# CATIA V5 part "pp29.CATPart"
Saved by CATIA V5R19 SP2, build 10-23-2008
Part number: pp29
Bounding box of the stored display mesh (mm): x -15 to -10, y -102.25 to 75.093, z -52.25 to 37.742
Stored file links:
  C:\Users\Welcome\Documents\thinkm2\pp29.CATPart
  C:\Users\Welcome\Documents\thinkm2\Brasmeca.CATProduct
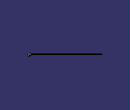
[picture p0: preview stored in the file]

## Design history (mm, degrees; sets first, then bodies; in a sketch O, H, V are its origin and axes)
AxisSystem1: origin (0, 0, 0), X (1, 0, 0), Y (0, 1, 0), Z (0, 0, 1)
Set1
  Plane1: linked copy from another document
  Line1: linked copy from another document
  Plane2: linked copy from another document
Body1 (main body)
  Sketch1 on Plane1, origin (-15, 0, 0), H (0, 1, 0), V (0, 0, 1)
    circle A1 centre (-100, -50) radius 2.25
    reference projected point E1 (-100, -50) from Line1
    radius A1 = 2.25
    distance A1 E1 = 2.25
  Pad1: profile Sketch1, direction (1, 0, 0), length 5
  Sketch2 on Plane2, origin (0, 50, 25), H (1, 0, 0), V (0, -0.4472, 0.8944)
    line L1 (-14.9565, 0.3213) -> (-13.3173, 0.3213)
    line L2 (-13.3173, 0.3213) -> (-13.3173, -0.4106)
    line L3 (-13.3173, -0.4106) -> (-14.9565, -0.4106)
    line L4 (-14.9565, -0.4106) -> (-14.9565, 0.3213)
  Pad2: profile Sketch2, direction (0, -0.8944, -0.4472), length 167
  Pad3: profile Sketch2, direction (0, 0.8944, 0.4472), length 27.85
